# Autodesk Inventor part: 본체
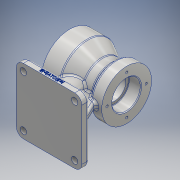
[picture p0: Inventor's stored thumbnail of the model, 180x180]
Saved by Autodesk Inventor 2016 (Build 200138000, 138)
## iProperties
Created: 2019-01
Part Number: 본체
Material: 알루미늄 6061
Document SubType Name: Modeling
Designer: 605-12
Density: 2.7 g/cm^3
Appearance: 알루미늄 - 평지
Mass: 898.816 g
Surface Area: 600.964 cm^2
Volume: 332.895 cm^3
Author: 605-12
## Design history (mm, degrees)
sketch "스케치1"
  geometry: L1 (0, 0)-(0, 40); L2 (0, 40)-(25, 40); L3 (25, 40)-(45.785, 28); L4 (45.785, 28)-(59.126, 28); L5 (59.126, 28)-(65, 35); L6 (65, 35)-(80, 35); L7 (80, 35)-(80, 0); L8 (80, 0)-(0, 0); L9 (0, 26)-(19, 26); L10 (20, 25)-(20, 16); L11 (20, 16)-(63, 16); L12 (63, 16)-(63, 19.4); L13 (63.6, 20)-(80, 20); A1 r 1 centre (19, 25) between (20, 25) and (19, 26); A2 r 0.6 centre (63.6, 19.4) between (63.6, 20) and (63, 19.4)
  constraints: 26 end point, 7 perpendicular, 4 point on circle, 4 tangent, 2 centre point, 2 parallel, 2 point on line, 1 horizontal, 1 vertical
  dimensions: "d0" = 80 diameter of L2 L8; "d1" = 56 diameter of L4 L8; "d2" = 70 diameter of L6 L8; "d4" = 30 deg angle of L4 L3; "d5" = 50 deg angle of L5 L4; "d6" = 25 distance of L1.end L2.end; "d7" = 80 distance between parallel lines of L7 L1; "d8" = 15 distance of L5.end L6.end; "d10" = 52 diameter of L9 L8; "d11" = 32 diameter of L11 L8; "d12" = 40 diameter of L13 L8; "d13" = 17 distance between parallel lines of L7 L12; "d14" = 20 distance between parallel lines of L10 L1; "d15" = 1 radius of A1; "d16" = 0.6 radius of A2
revolve "회전1" sketch "스케치1" stored, may be unused: angle "d17" = 90 deg
node "작업 평면1"
sketch "스케치2" dims "d32" = 10, "d39" = 10
  geometry: L1 (-15, -46)-(-87, -46); L2 (-97, -36)-(-97, 36); L3 (-87, 46)-(-15, 46); L4 (-5, 36)-(-5, -36); L5 (-5, -46)-(-97, 46); L6 (-97, -46)-(-5, 46); C1 r 16 at (-35, 0); C2 r 4.5 at (-87, -36); C3 r 4.5 at (-15, -36); C4 r 4.5 at (-15, 36); C5 r 4.5 at (-87, 36); A1 r 10 centre (-15, -36) between (-15, -46) and (-5, -36); A2 r 10 centre (-87, -36) between (-97, -36) and (-87, -46); A3 r 10 centre (-87, 36) between (-87, 46) and (-97, 36); A4 r 10 centre (-15, 36) between (-5, 36) and (-15, 46); 3 further points
  constraints: 12 end point, 9 centre point, 9 point on line, 8 point on circle, 8 tangent, 3 equal radius, 3 midpoint, 2 horizontal, 2 parallel, 1 horizontal alignment, 1 perpendicular, 1 vertical, 6 other
  dimensions: "d19" = 92 distance of L6.start L5.end; "d20" = 92 distance of L5.start L6.start; "d21" = 5 distance from line of L4 point (0, 0); "d22" = 32 diameter of C1; "d23" = 46 distance from line of L1 C1.centre; "d24" = 30 distance from line of C1.centre L4; "d25" = 10 radius of A1; "d26" = 9 diameter of C2; "d29" = 72 distance of C2.centre C3.centre; "d36" = 72 distance of C3.centre C4.centre
extrude "돌출1" join sketch "스케치2" distance "d41" = 10; taper "d42" = 0 deg
extrude "돌출2" join sketch "스케치2" stored distance "d43" = 10; taper "d44" = 0 deg
sketch "스케치3"
  geometry: L1 (87, -70)-(64.514, -21.778); L2 (64.514, -21.778)-(34.514, -21.778); L3 (34.514, -21.778)-(34.514, -70); L4 (34.514, -70)-(87, -70); L5 (87, -70)-(15, -70) reference; L6 (97, -80)-(97, -70) reference; 1 further point
  constraints: 8 end point, 1 collinear, 1 horizontal alignment, 1 perpendicular, 1 vertical
  dimensions: "d45" = 10 distance from line of L1.start L6; "d46" = 25 deg angle of L6 L1; "d47" = 48.22172 distance of L2.end L3.end; "d48" = 30 distance of L1.end L2.end
extrude "돌출3" join sketch "스케치3" stored distance "d49" = 10; taper "d50" = 0 deg
sketch "스케치4" dims "d51" = 66
  geometry: 6 further points
  constraints: 2 vertical alignment, 1 coincident, 7 other
  dimensions: "d54" = 360 deg dimension on point (0, 0) point (0, 33) (derived)
hole "구멍1" sketch "스케치4" at (0, 33), (-33, 0), (0, -33), (33, 0) diameter "d56" = 3.242; stored, may be unused: countersink angle "d60" = 90 deg, drill point angle "d62" = 118 deg; dims "d57" = 9, "d58" = 4, "d59" = 2, "d61" = 11
sketch "스케치5" dims "d63" = 55
  geometry: 6 further points
  constraints: 2 vertical alignment, 1 coincident, 7 other
  dimensions: "d66" = 360 deg dimension on point (0, 0) point (0, 27.5) (derived)
hole "구멍2" sketch "스케치5" at (0, 27.5), (-27.5, 0), (0, -27.5), (27.5, 0) diameter "d68" = 3.242; stored, may be unused: countersink angle "d72" = 90 deg, drill point angle "d74" = 118 deg; dims "d69" = 9, "d70" = 4, "d71" = 2, "d73" = 11
sketch "스케치6"
  geometry: L1 (0, 10)-(72, 10) reference; L2 (-10, 0)-(-10, 10) reference; L3 (72, 0)-(82, 0) reference; 2 further points
  constraints: 1 other
  dimensions: "d76" = 46 distance from line of point (36, 4) L2; "d77" = 4 distance from line of L3 point (36, 4)
feature "엠보싱1" sketch "스케치6" dims "d19" = 92, "d20" = 92, "d21" = 5, "d22" = 32, "d23" = 46, "d24" = 30, "d25" = 10, "d26" = 9, "d29" = 72, "d36" = 72, "d78" = 0.5, "d79" = 0
fillet "모깎기1" dims "d80" = 3
fillet "모깎기2" dims "d81" = 3
chamfer "모따기2" distance "d85" = 1; stored, may be unused: second distance "d86" = 2, angle "d87" = 45 deg
node "솔리드1"
